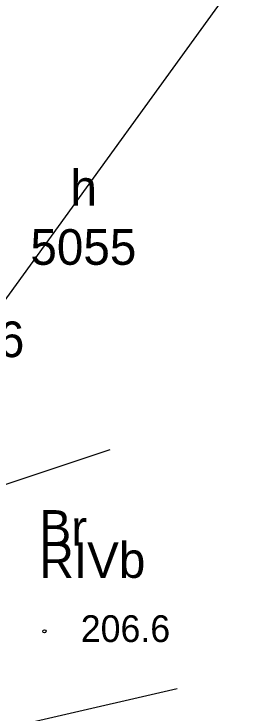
# Model space of a CAD drawing. Extents: x 6512606 to 6513006, y 6022524 to 6022728.
# Drawn here: x 6512872.32 to 6512879.34, y 6022603.95 to 6022623.56 of the extents above; entities that cross this region are included whole.
import ezdxf

# ---------------------------------------------------------------- set-up
doc = ezdxf.new("R2010")
doc.units = 0
for name, color, linetype in [('209-oznaczenie konturu klasyfikacyjnego', 7, 'Continuous'), ('210-oznaczenie konturu użytku gruntowego', 7, 'Continuous'), ('211-numer działki ewidencyjnej', 7, 'Continuous'), ('312-oznaczenie budynku ewidencyjnego', 7, 'Continuous'), ('312-oznaczenie budynku ewidencyjnego-Atr117', 7, 'Continuous'), ('4', 7, 'Continuous'), ('budynek projektowany (powierzchnia)', 7, 'Continuous'), ('Default', 7, 'Continuous'), ('maxp_opisy', 7, 'Continuous'), ('przewód wodociągowy (linia)', 7, 'Continuous'), ('punkt wysokościowy naturalny', 7, 'Continuous'), ('punkt wysokościowy naturalny-Atr2', 7, 'Continuous')]:
    doc.layers.add(name, color=color, linetype=linetype)

# ---------------------------------------------------------------- blocks, each defined once
blk = doc.blocks.new('PW01')
at = {"layer": 'Default'}
blk.add_circle((0, 0), 0.45, dxfattribs=at)

msp = doc.modelspace()

# ---------------------------------------------------------------- linework, layer by layer
at = {"layer": 'budynek projektowany (powierzchnia)'}
msp.add_lwpolyline([(6512876.905, 6022604.629), (6512866.3, 6022602.19), (6512866.5, 6022601.27), (6512865.79, 6022601.1), (6512863.94, 6022609.18), (6512865.92, 6022609.63), (6512865.01, 6022613.81), (6512862.96, 6022613.3), (6512860.72, 6022623.09)], dxfattribs=at)
at = {"layer": 'maxp_opisy'}
msp.add_lwpolyline([(6512856.121, 6022593.53), (6512879.345, 6022625.572), (6512868.61, 6022653.292)], dxfattribs=at)
at = {"layer": 'przewód wodociągowy (linia)'}
msp.add_lwpolyline([(6512865.1, 6022610.5), (6512870.21, 6022609.74), (6512875.021, 6022611.337)], dxfattribs=at)

# ---------------------------------------------------------------- block references
at = {"layer": 'punkt wysokościowy naturalny', "xscale": 0.1, "yscale": 0.10000000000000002}
msp.add_blockref('PW01', (6512873.18, 6022606.24), dxfattribs=at)

# ---------------------------------------------------------------- texts
at = {"layer": '209-oznaczenie konturu klasyfikacyjnego'}
msp.add_text('RIVb', height=1, dxfattribs=at).set_placement((6512873.04, 6022607.74))
at = {"layer": '210-oznaczenie konturu użytku gruntowego'}
msp.add_text('Br', height=1, dxfattribs=at).set_placement((6512873.04, 6022608.64))
at = {"layer": '211-numer działki ewidencyjnej'}
msp.add_text('156/6', height=1, dxfattribs=at).set_placement((6512869.27, 6022613.93))
at = {"layer": '312-oznaczenie budynku ewidencyjnego'}
msp.add_text('5055', height=1, dxfattribs=at).set_placement((6512872.785, 6022616.52))
at = {"layer": '312-oznaczenie budynku ewidencyjnego-Atr117'}
msp.add_text('h', height=1, dxfattribs=at).set_placement((6512873.91, 6022618.18))
at = {"layer": '4'}
msp.add_text('156/6', height=1, dxfattribs=at).set_placement((6512869.27, 6022613.93))
at = {"layer": 'punkt wysokościowy naturalny-Atr2'}
msp.add_text('206.6', height=0.75, dxfattribs=at).set_placement((6512874.2, 6022605.94))

doc.saveas('drawing.dxf')
